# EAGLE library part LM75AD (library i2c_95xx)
Digital Temperature Sensor and Thermal Watchdog
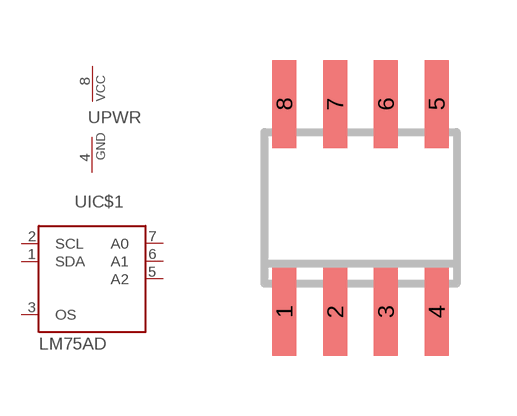
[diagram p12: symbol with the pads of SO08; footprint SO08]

Designator prefix -; gates IC$1=LM75A PWR=PWRN

## LM75AD  [SO08]
1  IC$1:SDA
2  IC$1:SCL  in
3  IC$1:OS  out
4  PWR:GND  pwr
5  IC$1:A2  in
6  IC$1:A1  in
7  IC$1:A0  in
8  PWR:VCC  pwr

## Footprint SO08 (pad centres in mm)
smd 0.6 x 2.2: 1 -1.905,-2.6; 2 -0.635,-2.6; 3 0.635,-2.6; 4 1.905,-2.6; 5 1.905,2.6; 6 0.635,2.6; 7 -0.635,2.6; 8 -1.905,2.6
